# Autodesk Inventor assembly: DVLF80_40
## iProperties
Created: 2010-03
Part Number: DVLF80_40
Document SubType Name: Assembly
Designer: TB
Mass: 1870.36 g
Surface Area: 2510.35 cm^2
Volume: 1870.36 cm^3
Density: 1 g/cm^3
Description: KM DVLF 80/40 - 100 mm
Slaglengde: 100.000 mm
Author: TB
